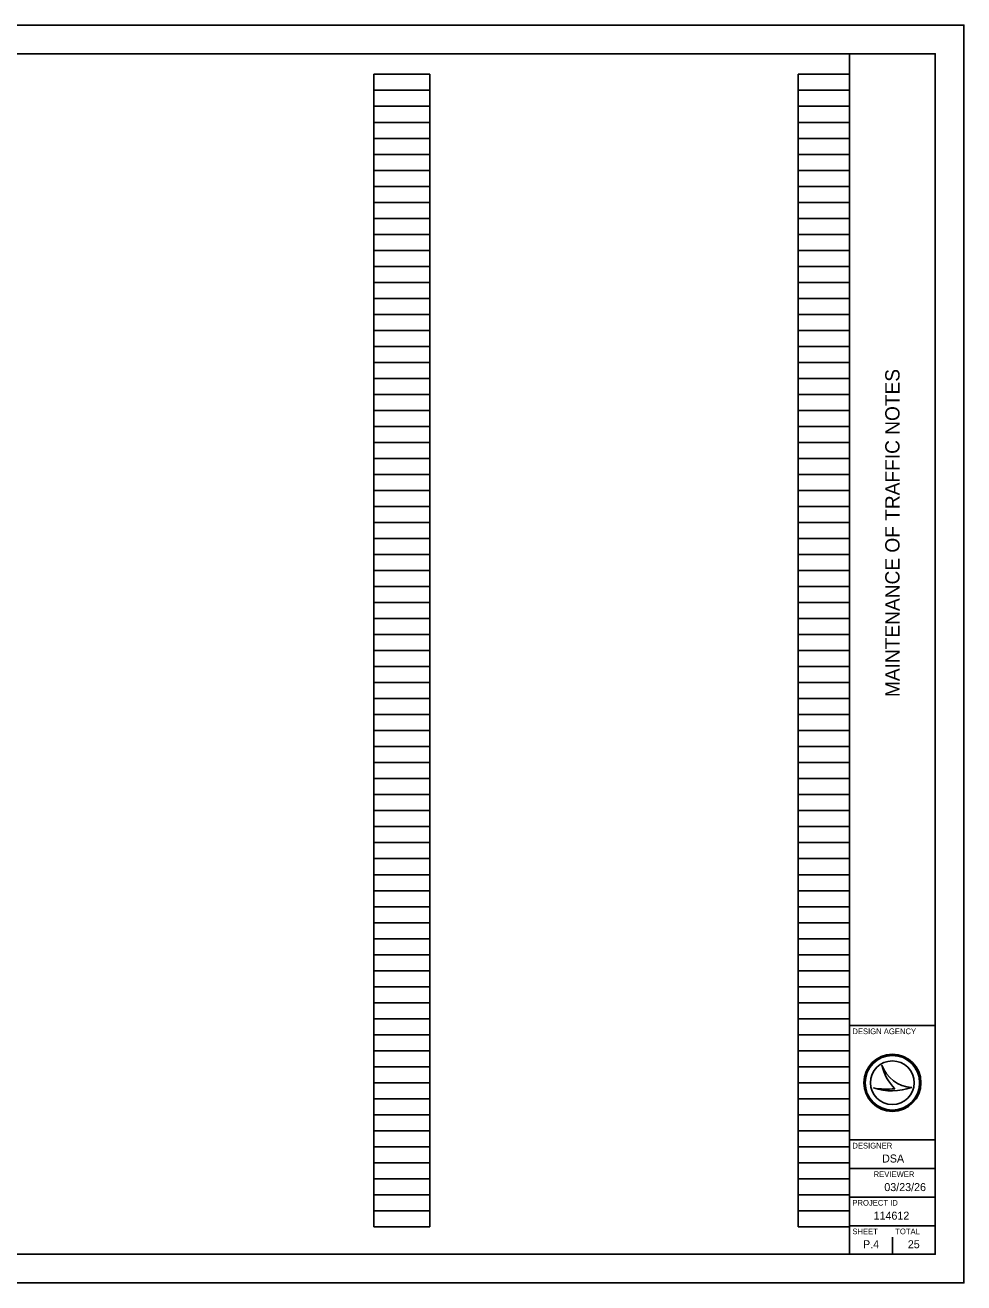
# Model space of a CAD drawing. Extents: x 0 to 34, y 0 to 22.
# Drawn here: x 17.58 to 34, y 0 to 22 of the extents above; entities that cross this region are included whole.
import ezdxf

# ---------------------------------------------------------------- set-up
doc = ezdxf.new("R2010")
doc.units = 0
for name, color, linetype in [('SC_Scratch1', 7, 'Continuous'), ('SH_Border', 7, 'Continuous'), ('SH_Cut_Line', 7, 'Continuous'), ('SH_Data', 7, 'Continuous')]:
    doc.layers.add(name, color=color, linetype=linetype)

msp = doc.modelspace()

# ---------------------------------------------------------------- linework, layer by layer
at = {"layer": 'SC_Scratch1'}
for p, q in [((23.68, 0.98), (23.68, 21.14)), ((23.68, 21.14), (24.66, 21.14)), ((24.66, 0.98), (24.66, 21.14)), ((31.1, 0.98), (31.1, 21.14)), ((31.1, 21.14), (32, 21.14)), ((32, 0.98), (32, 21.14)), ((23.68, 20.86), (24.66, 20.86)), ((31.1, 20.86), (32, 20.86)), ((23.68, 20.58), (24.66, 20.58)), ((31.1, 20.58), (32, 20.58)), ((23.68, 20.3), (24.66, 20.3)), ((31.1, 20.3), (32, 20.3)), ((23.68, 20.02), (24.66, 20.02)), ((31.1, 20.02), (32, 20.02)), ((23.68, 19.74), (24.66, 19.74)), ((31.1, 19.74), (32, 19.74)), ((23.68, 19.46), (24.66, 19.46)), ((31.1, 19.46), (32, 19.46)), ((23.68, 19.18), (24.66, 19.18)), ((31.1, 19.18), (32, 19.18)), ((23.68, 18.9), (24.66, 18.9)), ((31.1, 18.9), (32, 18.9)), ((23.68, 18.62), (24.66, 18.62)), ((31.1, 18.62), (32, 18.62)), ((23.68, 18.34), (24.66, 18.34)), ((31.1, 18.34), (32, 18.34)), ((23.68, 18.06), (24.66, 18.06)), ((31.1, 18.06), (32, 18.06)), ((23.68, 17.78), (24.66, 17.78)), ((31.1, 17.78), (32, 17.78)), ((23.68, 17.5), (24.66, 17.5)), ((31.1, 17.5), (32, 17.5)), ((23.68, 17.22), (24.66, 17.22)), ((31.1, 17.22), (32, 17.22)), ((23.68, 16.94), (24.66, 16.94)), ((31.1, 16.94), (32, 16.94)), ((23.68, 16.66), (24.66, 16.66)), ((31.1, 16.66), (32, 16.66)), ((23.68, 16.38), (24.66, 16.38)), ((31.1, 16.38), (32, 16.38)), ((23.68, 16.1), (24.66, 16.1)), ((31.1, 16.1), (32, 16.1)), ((23.68, 15.82), (24.66, 15.82)), ((31.1, 15.82), (32, 15.82)), ((23.68, 15.54), (24.66, 15.54)), ((31.1, 15.54), (32, 15.54)), ((23.68, 15.26), (24.66, 15.26)), ((31.1, 15.26), (32, 15.26)), ((23.68, 14.98), (24.66, 14.98)), ((31.1, 14.98), (32, 14.98)), ((23.68, 14.7), (24.66, 14.7)), ((31.1, 14.7), (32, 14.7)), ((23.68, 14.42), (24.66, 14.42)), ((31.1, 14.42), (32, 14.42)), ((23.68, 14.14), (24.66, 14.14)), ((31.1, 14.14), (32, 14.14)), ((23.68, 13.86), (24.66, 13.86)), ((31.1, 13.86), (32, 13.86)), ((23.68, 13.58), (24.66, 13.58)), ((31.1, 13.58), (32, 13.58)), ((23.68, 13.3), (24.66, 13.3)), ((31.1, 13.3), (32, 13.3)), ((23.68, 13.02), (24.66, 13.02)), ((31.1, 13.02), (32, 13.02)), ((23.68, 12.74), (24.66, 12.74)), ((31.1, 12.74), (32, 12.74)), ((23.68, 12.46), (24.66, 12.46)), ((31.1, 12.46), (32, 12.46)), ((23.68, 12.18), (24.66, 12.18)), ((31.1, 12.18), (32, 12.18)), ((23.68, 11.9), (24.66, 11.9)), ((31.1, 11.9), (32, 11.9)), ((23.68, 11.62), (24.66, 11.62)), ((31.1, 11.62), (32, 11.62)), ((23.68, 11.34), (24.66, 11.34)), ((31.1, 11.34), (32, 11.34)), ((23.68, 11.06), (24.66, 11.06)), ((31.1, 11.06), (32, 11.06)), ((23.68, 10.78), (24.66, 10.78)), ((31.1, 10.78), (32, 10.78)), ((23.68, 10.5), (24.66, 10.5)), ((31.1, 10.5), (32, 10.5)), ((23.68, 10.22), (24.66, 10.22)), ((31.1, 10.22), (32, 10.22)), ((23.68, 9.94), (24.66, 9.94)), ((31.1, 9.94), (32, 9.94)), ((23.68, 9.66), (24.66, 9.66)), ((31.1, 9.66), (32, 9.66)), ((23.68, 9.38), (24.66, 9.38)), ((31.1, 9.38), (32, 9.38)), ((23.68, 9.1), (24.66, 9.1)), ((31.1, 9.1), (32, 9.1)), ((23.68, 8.82), (24.66, 8.82)), ((31.1, 8.82), (32, 8.82)), ((23.68, 8.54), (24.66, 8.54)), ((31.1, 8.54), (32, 8.54)), ((23.68, 8.26), (24.66, 8.26)), ((31.1, 8.26), (32, 8.26)), ((23.68, 7.98), (24.66, 7.98)), ((31.1, 7.98), (32, 7.98)), ((23.68, 7.7), (24.66, 7.7)), ((31.1, 7.7), (32, 7.7)), ((23.68, 7.42), (24.66, 7.42)), ((31.1, 7.42), (32, 7.42)), ((23.68, 7.14), (24.66, 7.14)), ((31.1, 7.14), (32, 7.14)), ((23.68, 6.86), (24.66, 6.86)), ((31.1, 6.86), (32, 6.86)), ((23.68, 6.58), (24.66, 6.58)), ((31.1, 6.58), (32, 6.58)), ((23.68, 6.3), (24.66, 6.3)), ((31.1, 6.3), (32, 6.3)), ((23.68, 6.02), (24.66, 6.02)), ((31.1, 6.02), (32, 6.02)), ((23.68, 5.74), (24.66, 5.74)), ((31.1, 5.74), (32, 5.74)), ((23.68, 5.46), (24.66, 5.46)), ((31.1, 5.46), (32, 5.46)), ((23.68, 5.18), (24.66, 5.18)), ((31.1, 5.18), (32, 5.18)), ((23.68, 4.9), (24.66, 4.9)), ((31.1, 4.9), (32, 4.9)), ((23.68, 4.62), (24.66, 4.62)), ((31.1, 4.62), (32, 4.62)), ((23.68, 4.34), (24.66, 4.34)), ((31.1, 4.34), (32, 4.34)), ((23.68, 4.06), (24.66, 4.06)), ((31.1, 4.06), (32, 4.06)), ((23.68, 3.78), (24.66, 3.78)), ((31.1, 3.78), (32, 3.78)), ((23.68, 3.5), (24.66, 3.5)), ((31.1, 3.5), (32, 3.5)), ((23.68, 3.22), (24.66, 3.22)), ((31.1, 3.22), (32, 3.22)), ((23.68, 2.94), (24.66, 2.94)), ((31.1, 2.94), (32, 2.94)), ((23.68, 2.66), (24.66, 2.66)), ((31.1, 2.66), (32, 2.66)), ((23.68, 2.38), (24.66, 2.38)), ((31.1, 2.38), (32, 2.38)), ((23.68, 2.1), (24.66, 2.1)), ((31.1, 2.1), (32, 2.1)), ((23.68, 1.82), (24.66, 1.82)), ((31.1, 1.82), (32, 1.82)), ((23.68, 1.54), (24.66, 1.54)), ((31.1, 1.54), (32, 1.54)), ((23.68, 1.26), (24.66, 1.26)), ((31.1, 1.26), (32, 1.26)), ((23.68, 0.98), (24.66, 0.98)), ((31.1, 0.98), (32, 0.98))]:
    msp.add_line(p, q, dxfattribs=at)
at = {"layer": 'SH_Border'}
for p, q in [((32, 0.5), (32, 21.5)), ((32, 4.5), (33.5, 4.5)), ((32, 2.5), (33.5, 2.5)), ((32, 2), (33.5, 2)), ((32, 1.5), (33.5, 1.5)), ((32, 1), (33.5, 1))]:
    msp.add_line(p, q, dxfattribs=at)
msp.add_lwpolyline([(1.5, 21.5), (33.5, 21.5), (33.5, 0.5), (1.5, 0.5)], close=True, dxfattribs=at)
at = {"layer": 'SH_Cut_Line'}
msp.add_lwpolyline([(0, 0), (34, 0), (34, 22), (0, 22)], close=True, dxfattribs=at)
at = {"layer": 'SH_Data'}
for p, q in [((32.567, 3.81), (32.567, 3.81)), ((32.417, 3.41), (32.417, 3.41)), ((32.75, 3.5), (32.75, 3.5)), ((33.087, 3.419), (33.087, 3.419)), ((32.375, 0.675), (32.375, 0.675)), ((32.75, 0.5), (32.75, 0.8))]:
    msp.add_line(p, q, dxfattribs=at)
for radius in [0.5, 0.477, 0.477, 0.382]:
    msp.add_circle((32.75, 3.5), radius, dxfattribs=at)
for centre, radius, start, end in [((33.116, 3.998), 0.58, 198.9257, 198.9319), ((33.347, 3.97), 0.796, 191.6379, 191.6421), ((33.116, 3.998), 0.58, 198.9319, 267.1657), ((33.347, 3.97), 0.796, 191.6421, 226.0947), ((32.739, 4.37), 1.013, 251.4576, 290.0832), ((32.648, 4.654), 1.266, 259.4964, 259.4995), ((32.739, 4.37), 1.013, 251.4527, 251.4576), ((32.648, 4.654), 1.266, 259.4995, 276.6672)]:
    msp.add_arc(centre, radius, start, end, dxfattribs=at)

# ---------------------------------------------------------------- texts
msp.add_text('MAINTENANCE OF TRAFFIC NOTES', height=0.25, rotation=90, dxfattribs=at).set_placement((32.875, 10.247))
for s, height, p in [('DESIGN AGENCY', 0.1, (32.05, 4.35)), ('DESIGNER', 0.1, (32.05, 2.35)), ('DSA', 0.14, (32.57, 2.105)), ('REVIEWER', 0.1, (32.422, 1.85)), ('03/23/26', 0.14, (32.609, 1.605)), ('PROJECT ID', 0.1, (32.05, 1.35)), ('114612', 0.14, (32.421, 1.105)), ('SHEET', 0.1, (32.05, 0.85)), ('TOTAL', 0.1, (32.8, 0.85)), ('P.4', 0.14, (32.237, 0.605)), ('25', 0.14, (33.02, 0.605))]:
    msp.add_text(s, height=height, dxfattribs=at).set_placement(p)

doc.saveas('drawing.dxf')
